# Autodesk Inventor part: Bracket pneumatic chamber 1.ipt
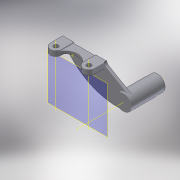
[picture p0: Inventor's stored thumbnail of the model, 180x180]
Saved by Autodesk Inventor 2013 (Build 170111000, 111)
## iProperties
Created: 2005-03
Part Number: Bracket pneumatic chamber 1.ipt
Material: Steel, Mild
Document SubType Name: Modeling
Designer: salex
Manufacturer: Standard
Standards Organization: Custom
Density: 7.86 g/cm^3
Mass: 4464.91 g
Surface Area: 799.794 cm^2
Volume: 568.055 cm^3
Author: salex
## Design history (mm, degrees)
sketch "Эскиз1"
  geometry: L1 (73.452, 28.786)-(73.452, -16.214); L2 (-86.548, 28.786)-(73.452, 28.786); L3 (-86.548, -16.214)-(-86.548, 28.786); L4 (-32.806, 3.786)-(38.179, 3.786); A1 r 20 centre (53.452, -16.214) between (34.99, -23.906) and (73.452, -16.214); A2 r 20 centre (-66.548, -16.214) between (-86.548, -16.214) and (-48.087, -23.906); A3 r 45 centre (-6.548, -41.214) between (34.99, -23.906) and (-48.087, -23.906)
  constraints: 8 end point, 6 point on circle, 5 tangent, 3 centre point, 2 horizontal, 2 vertical, 1 other
  dimensions: "d1" = 120 distance of A2.centre A1.centre; "d3" = 45 radius of A3; "d5" = 45 vertical distance of A2.centre L2.start; "d7" = 25 vertical distance of L2.start L4.start
extrude "ExtrusionMidplane1" new body sketch "Эскиз1" stored distance "d8" = 10; taper "d9" = 0 deg
node "WorkAxis1"
node "WorkAxis2"
node "WorkPlane1"
node "WorkPlane2"
node "РабПлоскость3"
node "WorkPlane3"
sketch "Эскиз2"
  geometry: L1 (-86.548, 28.786)-(-86.548, -16.214); L2 (-46.548, 28.786)-(-86.548, 28.786); L3 (-46.548, -16.214)-(-46.548, 28.786); L4 (21.448, 28.786)-(20.448, 28.786); A1 r 20 centre (-66.548, -16.214) between (-86.548, -16.214) and (-46.548, -16.214); 1 further point
  constraints: 8 end point, 2 point on circle, 2 tangent, 2 vertical, 1 centre point, 1 coincident, 1 collinear, 1 horizontal, 1 horizontal alignment, 2 other
extrude "ExtrusionBlind1" join sketch "Эскиз2" distance "d14" = 19; taper "d15" = 0 deg
node "РабОсь3"
node "РабОсь4"
pattern_linear "RectArray1" dims "d18" = 120
sketch "Эскиз8"
  geometry: L1 (-100, 9)-(-140, 9) reference; L2 (-120, 9)-(-120, 47.073); C1 r 28 at (-216, -75)
  constraints: 2 end point, 1 centre point, 1 midpoint, 1 perpendicular
  dimensions: "d55" = 56 diameter of C1; "d152" = 96 distance from line of C1.centre L2; "d153" = 84 distance from line of C1.centre L1
extrude "ExtrusionBlind7" join sketch "Эскиз8" distance "d58" = 24; taper "d59" = 0 deg
sketch "Эскиз9"
  geometry: C1 r 29 at (-216, -75); C2 r 28 at (-216, -75); C3 r 28 at (-216, -75) reference
  constraints: 2 centre point, 1 coincident, 1 concentric
  dimensions: "d63" = 58 diameter of C1
extrude "ExtrusionBlind8" join sketch "Эскиз9" distance "d64" = 100; taper "d65" = 0 deg
sketch "Эскиз10"
  geometry: L1 (160, 15)-(160, -6.025); L2 (0.292, 15)-(160, 15); L3 (31.605, 28.83)-(20, 15); L4 (167.5, 6.965)-(250.5, 54.885); L5 (160, 38)-(160, 37); L6 (-40.894, 30)-(-39.894, 30); L7 (0, 38)-(0, 37); L8 (160, 15)-(160, -4) reference; L9 (160, 15)-(120, 15) reference; L10 (0, 15)-(0, -4) reference; L11 (160, 0)-(20, 0); L12 (20, 0)-(20, 15); L13 (40, 0)-(120, 0) reference; L14 (160, 10.803)-(160, 0); L15 (160, 0)-(160, 15); L16 (160, 0)-(20, 0); L17 (20, 15)-(160, 15); C1 r 29 at (236, 80); C2 r 29 at (236, 80) reference; A1 r 15 centre (175, -6.025) between (167.5, 6.965) and (160, -6.025); A2 r 230 centre (207.795, -119.011) between (240.069, 108.713) and (31.605, 28.83); A3 r 29 centre (236, 80) between (250.5, 54.885) and (240.069, 108.713)
  constraints: 26 end point, 7 collinear, 6 point on circle, 5 tangent, 4 centre point, 3 concentric, 3 perpendicular, 3 point on line, 1 coincident, 1 horizontal, 1 vertical
  dimensions: "d73" = 30 deg angle of L2 L4; "d154" = 15 radius of A1; "d156" = 230 radius of A2; "d157" = 20 distance of L3.end L10.start; "d158" = 50 deg angle of L2 L3
extrude "ExtrusionBlind9" join sketch "Эскиз10" distance "d77" = 10; taper "d78" = 0 deg
node "РабОсь8"
node "РабОсь11"
node "РабОсь12"
node "РабПлоскость12"
node "РабОсь13"
node "РабОсь14"
node "РабПлоскость13"
node "РабТочка2"
body "Solid1"
sketch "Эскиз16"
  geometry: A1 r 20 centre (-120, 0) between (-140, 0) and (-100, 0) reference; 1 further point
hole "Hole5" sketch "Эскиз16" diameter "d115" = 18; stored, may be unused: countersink angle "d119" = 90 deg, drill point angle "d121" = 118 deg; dims "d116" = 6, "d117" = 4, "d118" = 2, "d120" = 8
sketch "Эскиз17"
  geometry: A1 r 20 centre (0, 0) between (-20, 0) and (-18.462, -7.692) reference; 1 further point
hole "Hole6" sketch "Эскиз17" diameter "d122" = 18; stored, may be unused: countersink angle "d126" = 90 deg, drill point angle "d128" = 118 deg; dims "d123" = 6, "d124" = 4, "d125" = 2, "d127" = 8
other parameters: "d2" = 45 (derived), "d4" = 45 (derived), "d6" = 25 (derived), "d10" = 0, "d11" = 0, "d12" = -15, "d13" = -129, "d22" = 0, "d23" = 0, "d24" = 16 (derived), "d26" = 96 (derived), "d28" = 114 (derived), "d30" = 57 (derived), "d34" = 15 (derived), "d36" = 48 (derived), "d38" = 25 deg (derived), "d50" = 0, "d53" = 0, "d54" = 56 (derived), "d60" = 0, "d61" = 0, "d62" = 58 (derived), "d66" = 15 (derived), "d70" = 155 (derived), "d72" = 25 deg (derived), "d74" = 30 deg (derived), "d76" = 0 (derived), "d80" = 0 (derived), "d81" = 146 (derived), "d83" = 54 (derived), "d129" = 135 deg (derived), "d131" = 35 (derived), "d133" = 20.5 (derived), "d135" = 22.5 (derived), "d137" = 42 (derived), "d159" = 90 deg
